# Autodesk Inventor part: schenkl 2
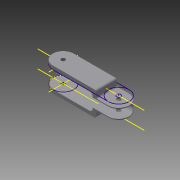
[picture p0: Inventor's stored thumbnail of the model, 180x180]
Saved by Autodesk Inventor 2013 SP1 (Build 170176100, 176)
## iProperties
Created: 2012-11
Part Number: schenkl 2
Material: Allgemein
Document SubType Name: Modeling
Designer: macuser
Density: 1 g/cm^3
Author: macuser
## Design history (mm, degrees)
sketch "Skizze1"
  geometry: L1 (0, -42)-(0, 42) reference; L2 (-74, 0)-(234, 0) reference; L3 (0, 30)-(160, 30); L4 (0, -30)-(160, -30); C1 r 6 at (0, 0); C2 r 6 at (160, 0); A1 r 30 centre (0, 0) between (0, 30) and (0, -30); A2 r 30 centre (160, 0) between (160, 30) and (160, -30); 1 further point
  constraints: 4 centre point, 4 end point, 4 point on circle, 2 coincident, 2 parallel, 2 point on line, 2 tangent
  dimensions: "d0" = 60 diameter of A1; "d1" = 60 diameter of A2; "d2" = 0 distance from line of L1 A1.centre; "d3" = 160 distance of A2.centre point (0, 0); "d4" = 12 diameter of C1; "d5" = 12 diameter of C2
extrude "Extrusion1" new body sketch "Skizze1" distance "d6" = 10; taper "d7" = 0 deg
sketch "Skizze2"
  geometry: L1 (0, -42)-(0, 42) reference; L2 (-74, 0)-(234, 0) reference; L3 (5, 30)-(155, 30); L4 (5, 30)-(5, 25); L5 (5, 25)-(155, 25); L6 (155, 25)-(155, 30); C1 r 30 at (0, 0); A1 r 30 centre (0, 0) between (0, 30) and (0, -30) reference
  constraints: 8 end point, 2 parallel, 1 centre point, 1 coincident, 1 perpendicular
  dimensions: "d8" = 150 distance of L3.start L3.end; "d9" = 5 distance from line of L1 L3.start; "d12" = 5 distance of L3.start L4.end; "d13" = 30 distance between parallel lines of L2 L3; "d31" = 5 distance of L5.end L3.end; "d44" = 60 diameter of C1
extrude "Extrusion5" join sketch "Skizze2" distance "d32" = 50; taper "d33" = 0 deg
sketch "Skizze4"
  geometry: L1 (0, -42)-(0, 42) reference; L2 (-74, 0)-(234, 0) reference; L3 (0, 30)-(160, 30); L4 (0, -30)-(160, -30); C1 r 6 at (0, 0); C2 r 6 at (160, 0); A1 r 30 centre (0, 0) between (0, 30) and (0, -30); A2 r 30 centre (160, 0) between (160, 30) and (160, -30); 1 further point
  constraints: 5 point on circle, 4 centre point, 4 end point, 3 coincident, 2 point on line, 2 tangent
  dimensions: "d34" = 60 diameter of A1; "d35" = 60 diameter of A2; "d36" = 0 distance from line of L2 A2.centre; "d37" = 160 distance of A1.centre A2.centre; "d38" = 12 diameter of C1; "d39" = 12 diameter of C2
extrude "Extrusion6" join sketch "Skizze4" distance "d40" = 10; taper "d41" = 0 deg
extrude "Extrusion7" cut sketch "Skizze4" distance "d42" = 10; taper "d43" = 0 deg
sketch "Skizze5"
  geometry: C1 r 6 at (0, 0) reference; C2 r 32.5 at (0, 0)
  constraints: 1 centre point, 1 coincident
  dimensions: "d46" = 65 diameter of C2
extrude "Extrusion8" cut sketch "Skizze5" distance "d47" = 50; taper "d48" = 0 deg
sketch "Skizze6"
  geometry: C1 r 6 at (160, 0) reference; C2 r 32.5 at (160, 0)
  constraints: 1 centre point, 1 coincident
  dimensions: "d50" = 65 diameter of C2
extrude "Extrusion9" cut sketch "Skizze6" distance "d51" = 50; taper "d52" = 0 deg
sketch "Skizze7"
  geometry: L1 (0, -30)-(160, -30) reference; L2 (160, 30)-(0, 30) reference; L3 (115, 30)-(115, -30); L4 (115, 30)-(160, 30); L5 (115, -30)-(160, -30); C1 r 6 at (160, 0) reference; C2 r 30 at (160, 0); C3 r 6 at (160, 0); A1 r 30 centre (160, 0) between (160, -30) and (160, 30) reference
  constraints: 6 end point, 2 centre point, 2 coincident, 2 point on line, 2 tangent, 1 perpendicular
  dimensions: "d53" = 60 diameter of C2; "d54" = 12 diameter of C3; "d55" = 45 distance from line of L3 C2.centre
extrude "Extrusion10" join sketch "Skizze7" distance "d56" = 60; taper "d57" = 0 deg
sketch "Skizze8"
  geometry: L1 (160, 30)-(0, 30) reference; L2 (0, -30)-(160, -30) reference; L3 (125, 30)-(125, -30); C1 r 6 at (160, 0) reference; C2 r 30 at (160, 0); C3 r 6 at (160, 0); A1 r 30 centre (160, 0) between (160, -30) and (160, 30) reference
  constraints: 2 centre point, 2 coincident, 2 concentric, 2 end point, 2 point on line, 1 perpendicular
  dimensions: "d58" = 35 distance from line of L3 C3.centre
extrude "Extrusion11" cut sketch "Skizze8" distance "d63" = 20; taper "d64" = 0 deg
sketch "Skizze9"
  geometry: L1 (-160, 30)-(0, 30) reference; L2 (0, -30)-(-160, -30) reference; L3 (-125, 30)-(-125, -30); C1 r 6 at (-160, 0) reference; C2 r 30 at (-160, 0); C3 r 6 at (-160, 0); A1 r 30 centre (-160, 0) between (-160, 30) and (-160, -30) reference
  constraints: 2 centre point, 2 coincident, 2 end point, 2 point on line, 1 concentric, 1 perpendicular
  dimensions: "d65" = 60 diameter of C2; "d66" = 35 distance from line of L3 C3.centre
extrude "Extrusion12" cut sketch "Skizze9" distance "d67" = 20; taper "d68" = 0 deg
fillet "Rundung1" dims "d69" = 5
fillet "Rundung2" dims "d70" = 10
sketch "Skizze10"
  geometry: L1 (30, 0)-(0, 0) reference; L2 (-34, 30)-(64, 30) reference; L3 (-20, -27)-(-20, 74.5) reference; L4 (5, 40)-(5, 0); L5 (25, 40)-(25, 0); A1 r 10 centre (15, 40) between (25, 40) and (5, 40); 1 further point
  constraints: 4 end point, 2 perpendicular, 2 point on circle, 2 point on line, 2 tangent, 1 centre point
  dimensions: "d81" = 20 diameter of A1; "d82" = 40 distance from line of L1 A1.centre; "d83" = 35 distance from line of A1.centre L3
extrude "Extrusion13" cut sketch "Skizze10" distance "d75" = 80; taper "d76" = 0 deg
sketch "Skizze11"
  geometry: L1 (0, 50)-(0, 0) reference; L2 (-94.767, -10)-(213.233, -10) reference; L3 (-20.767, -24)-(-20.767, 74) reference; L4 (84.233, 40)-(10, 40); L5 (84.233, 40)-(84.233, 10); L6 (84.233, 10)-(10, 10); L7 (10, 40)-(10, 10); A1 r 10 centre (84.233, 10) between (84.233, 0) and (94.233, 10) reference; A2 r 10 centre (84.233, 40) between (94.233, 40) and (84.233, 50) reference; 1 further point
  constraints: 8 end point, 3 perpendicular
  dimensions: "d77" = 10 distance from line of L1 L4.end; "d78" = 10 distance from line of L1 L6.end
extrude "Extrusion14" cut sketch "Skizze11" distance "d79" = 5; taper "d80" = 0 deg
node "Volumenkörper1"
